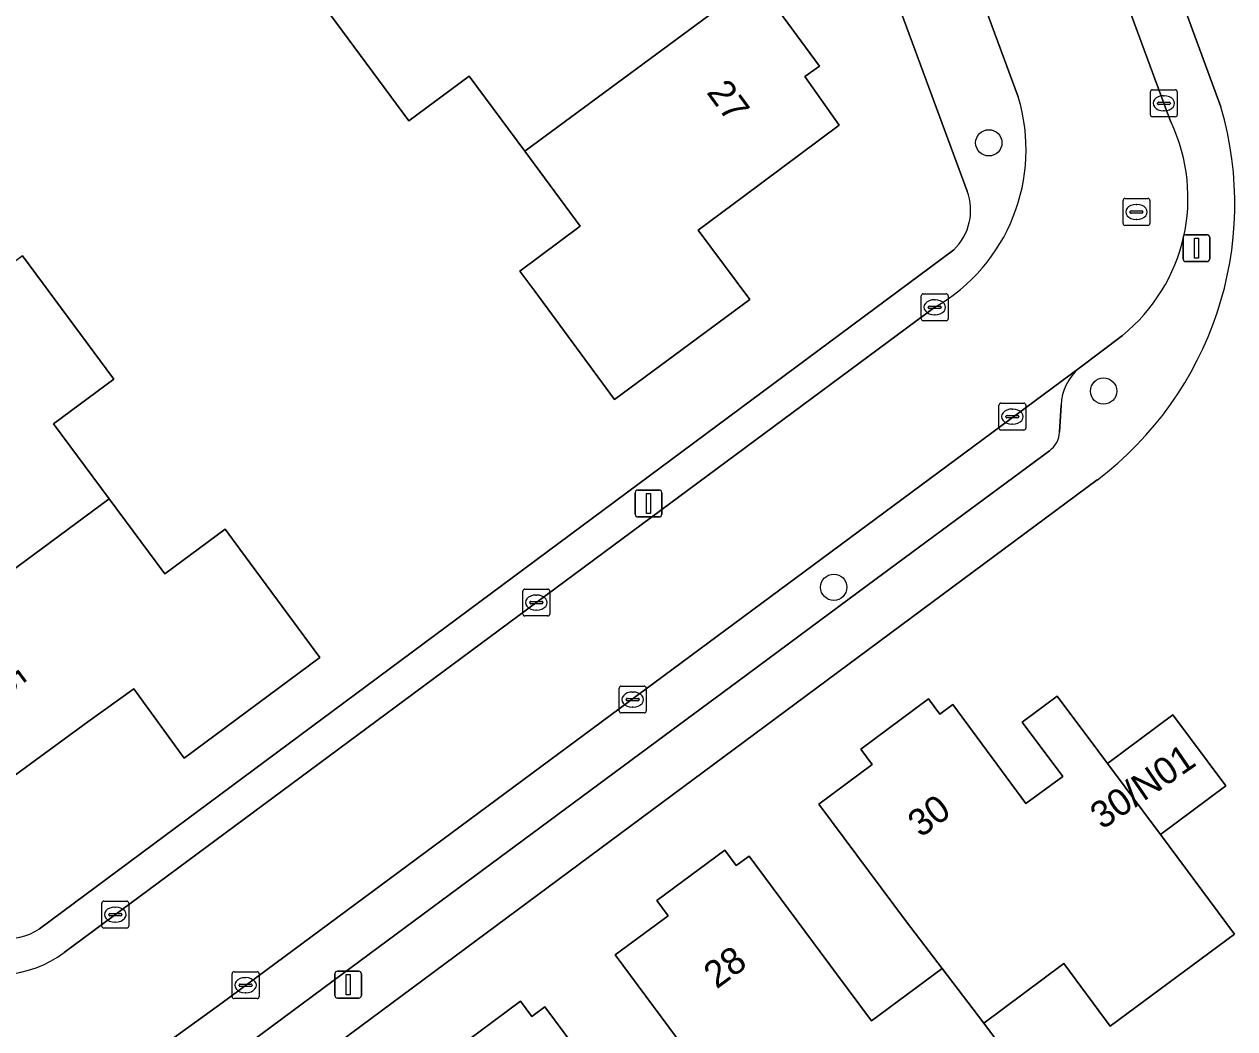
# Model space of a CAD drawing. Extents: x 163426 to 164192, y 380329 to 381641.
# Drawn here: x 163877.32 to 163922.34, y 381126.58 to 381163.93 of the extents above; entities that cross this region are included whole.
import ezdxf

# ---------------------------------------------------------------- set-up
doc = ezdxf.new("R2010")
doc.units = 0
for name, color, linetype in [('IMGEO_Boom', 7, 'Continuous'), ('IMGEO_Erf', 7, 'Continuous'), ('IMGEO_Kolk', 7, 'Continuous'), ('IMGEO_Lichtmast', 7, 'Continuous'), ('IMGEO_Pand', 7, 'Continuous'), ('IMGEO_Pand_nummerreeks', 7, 'Continuous'), ('IMGEO_Parkeervlak_open', 7, 'Continuous'), ('IMGEO_Rijbaan_lokaal_open', 7, 'Continuous'), ('IMGEO_Rioolput', 7, 'Continuous'), ('IMGEO_Voetpad_open', 7, 'Continuous')]:
    doc.layers.add(name, color=color, linetype=linetype)

msp = doc.modelspace()

# ---------------------------------------------------------------- linework, layer by layer
at = {"layer": 'IMGEO_Boom'}
for centre in [(163913.195, 381159.523), (163917.466, 381150.293), (163907.429, 381142.998)]:
    msp.add_circle(centre, 0.489, dxfattribs=at)
at = {"layer": 'IMGEO_Erf'}
for points in [[(163912.458, 381186.339), (163921.831, 381160.861)], [(163912.387, 381157.729), (163904.013, 381180.42)], [(163905.197, 381164.676), (163906.897, 381162.371), (163906.356, 381161.988), (163907.631, 381160.185), (163904.073, 381157.531), (163902.39, 381156.275), (163904.312, 381153.699), (163899.276, 381149.981), (163896.305, 381154.003), (163895.748, 381154.757), (163898, 381156.42), (163895.936, 381159.214), (163893.872, 381162.007), (163891.621, 381160.344), (163888.24, 381164.922)], [(163877.893, 381130.301), (163911.894, 381155.545)], [(163877.25, 381155.325), (163880.651, 381150.737), (163878.411, 381149.076), (163880.48, 381146.285), (163882.549, 381143.494), (163884.789, 381145.156), (163885.342, 381144.41), (163888.32, 381140.393), (163883.272, 381136.64), (163881.394, 381139.227), (163879.691, 381137.99), (163876.101, 381135.383)], [(163917.22, 381146.987), (163884.455, 381122.693), (163883.08, 381121.66), (163882.189, 381120.998)], [(163903.828, 381123.229), (163899.295, 381129.331), (163901.27, 381130.787), (163900.854, 381131.347), (163903.374, 381133.22), (163903.797, 381132.65), (163904.279, 381133.006), (163907.537, 381128.624), (163908.835, 381126.878), (163911.457, 381128.826), (163910.136, 381130.556), (163906.878, 381134.938), (163908.856, 381136.409), (163908.433, 381136.98), (163910.953, 381138.853), (163911.376, 381138.283), (163911.857, 381138.641), (163914.574, 381134.957), (163915.944, 381135.968), (163914.442, 381137.988), (163915.742, 381138.955), (163917.249, 381136.93), (163917.607, 381136.448), (163920.04, 381138.258), (163922.01, 381135.611), (163919.576, 381133.801), (163922.33, 381130.099), (163917.712, 381126.679), (163915.991, 381129.004), (163913.008, 381126.795), (163914.73, 381124.47)], [(163893.26, 381125.735), (163895.78, 381127.608), (163896.203, 381127.038), (163896.685, 381127.394), (163899.951, 381122.993)]]:
    msp.add_lwpolyline(points, dxfattribs=at)
for centre, radius, start, end in [((163909.481, 381157.262), 12.864, 306.9864, 16.2453), ((163910.502, 381157.007), 2.018, 313.594, 20.9653), ((163876.722, 381132.011), 2.072, 216.5753, 304.4017)]:
    msp.add_arc(centre, radius, start, end, dxfattribs=at)
at = {"layer": 'IMGEO_Kolk'}
for p, q in [((163919.205, 381160.568), (163919.205, 381161.42)), ((163919.28, 381161.494), (163920.132, 381161.494)), ((163919.693, 381161.274), (163919.718, 381161.274)), ((163920.206, 381161.42), (163920.206, 381160.568)), ((163919.464, 381160.988), (163919.464, 381161)), ((163919.902, 381160.951), (163919.504, 381160.951)), ((163919.507, 381161.037), (163919.905, 381161.037)), ((163919.948, 381161), (163919.948, 381160.988)), ((163920.132, 381160.494), (163919.28, 381160.494)), ((163919.716, 381160.714), (163919.691, 381160.714)), ((163910.684, 381152.983), (163910.684, 381153.835)), ((163910.759, 381153.909), (163911.611, 381153.909)), ((163911.172, 381153.689), (163911.197, 381153.689)), ((163911.685, 381153.835), (163911.685, 381152.983)), ((163910.943, 381153.403), (163910.943, 381153.415)), ((163911.381, 381153.366), (163910.983, 381153.366)), ((163910.986, 381153.452), (163911.384, 381153.452)), ((163911.195, 381153.129), (163911.17, 381153.129)), ((163911.427, 381153.415), (163911.427, 381153.403)), ((163911.611, 381152.909), (163910.759, 381152.909)), ((163913.572, 381148.918), (163913.572, 381149.77)), ((163913.647, 381149.844), (163914.499, 381149.844)), ((163914.06, 381149.624), (163914.085, 381149.624)), ((163914.573, 381149.77), (163914.573, 381148.918)), ((163913.831, 381149.338), (163913.831, 381149.35)), ((163914.269, 381149.301), (163913.871, 381149.301)), ((163913.874, 381149.387), (163914.272, 381149.387)), ((163914.083, 381149.064), (163914.058, 381149.064)), ((163914.315, 381149.35), (163914.315, 381149.338)), ((163914.499, 381148.844), (163913.647, 381148.844)), ((163895.865, 381142.004), (163895.865, 381142.856)), ((163895.94, 381142.93), (163896.792, 381142.93)), ((163896.866, 381142.856), (163896.866, 381142.004)), ((163896.124, 381142.424), (163896.124, 381142.436)), ((163896.562, 381142.387), (163896.164, 381142.387)), ((163896.167, 381142.473), (163896.565, 381142.473)), ((163896.353, 381142.71), (163896.378, 381142.71)), ((163896.608, 381142.436), (163896.608, 381142.424)), ((163896.792, 381141.93), (163895.94, 381141.93)), ((163896.376, 381142.15), (163896.351, 381142.15)), ((163899.451, 381138.398), (163899.451, 381139.25)), ((163899.526, 381139.324), (163900.378, 381139.324)), ((163900.452, 381139.25), (163900.452, 381138.398)), ((163899.71, 381138.818), (163899.71, 381138.83)), ((163900.148, 381138.781), (163899.75, 381138.781)), ((163899.753, 381138.867), (163900.151, 381138.867)), ((163899.939, 381139.104), (163899.964, 381139.104)), ((163900.194, 381138.83), (163900.194, 381138.818)), ((163900.378, 381138.324), (163899.526, 381138.324)), ((163899.962, 381138.544), (163899.937, 381138.544)), ((163880.205, 381130.401), (163880.205, 381131.253)), ((163880.28, 381131.327), (163881.132, 381131.327)), ((163880.693, 381131.107), (163880.718, 381131.107)), ((163881.206, 381131.253), (163881.206, 381130.401)), ((163880.464, 381130.821), (163880.464, 381130.833)), ((163880.902, 381130.784), (163880.504, 381130.784)), ((163880.507, 381130.87), (163880.905, 381130.87)), ((163880.948, 381130.833), (163880.948, 381130.821)), ((163881.132, 381130.327), (163880.28, 381130.327)), ((163880.716, 381130.547), (163880.691, 381130.547)), ((163885.052, 381127.777), (163885.052, 381128.629)), ((163885.127, 381128.703), (163885.979, 381128.703)), ((163885.54, 381128.483), (163885.565, 381128.483)), ((163886.053, 381128.629), (163886.053, 381127.777)), ((163885.311, 381128.197), (163885.311, 381128.209)), ((163885.749, 381128.16), (163885.351, 381128.16)), ((163885.354, 381128.246), (163885.752, 381128.246)), ((163885.563, 381127.923), (163885.538, 381127.923)), ((163885.795, 381128.209), (163885.795, 381128.197)), ((163885.979, 381127.703), (163885.127, 381127.703))]:
    msp.add_line(p, q, dxfattribs=at)
for points in [[(163919.205, 381160.568), (163919.205, 381161.42)], [(163919.28, 381161.494), (163920.132, 381161.494)], [(163920.206, 381161.42), (163920.206, 381160.568)], [(163920.132, 381160.494), (163919.28, 381160.494)], [(163910.684, 381152.983), (163910.684, 381153.835)], [(163910.759, 381153.909), (163911.611, 381153.909)], [(163911.685, 381153.835), (163911.685, 381152.983)], [(163911.611, 381152.909), (163910.759, 381152.909)], [(163913.572, 381148.918), (163913.572, 381149.77)], [(163913.647, 381149.844), (163914.499, 381149.844)], [(163914.573, 381149.77), (163914.573, 381148.918)], [(163914.499, 381148.844), (163913.647, 381148.844)], [(163895.865, 381142.004), (163895.865, 381142.856)], [(163895.94, 381142.93), (163896.792, 381142.93)], [(163896.866, 381142.856), (163896.866, 381142.004)], [(163896.792, 381141.93), (163895.94, 381141.93)], [(163899.451, 381138.398), (163899.451, 381139.25)], [(163899.526, 381139.324), (163900.378, 381139.324)], [(163900.452, 381139.25), (163900.452, 381138.398)], [(163900.378, 381138.324), (163899.526, 381138.324)], [(163880.205, 381130.401), (163880.205, 381131.253)], [(163880.28, 381131.327), (163881.132, 381131.327)], [(163881.206, 381131.253), (163881.206, 381130.401)], [(163881.132, 381130.327), (163880.28, 381130.327)], [(163885.052, 381127.777), (163885.052, 381128.629)], [(163885.127, 381128.703), (163885.979, 381128.703)], [(163886.053, 381128.629), (163886.053, 381127.777)], [(163885.979, 381127.703), (163885.127, 381127.703)]]:
    msp.add_lwpolyline(points, dxfattribs=at)
for centre, radius, start, end in [((163919.282, 381161.418), 0.0765, 91.552, 178.448), ((163919.282, 381161.418), 0.0765, 91.552, 178.448), ((163920.13, 381161.418), 0.0765, 1.552, 88.448), ((163920.13, 381161.418), 0.0765, 1.552, 88.448), ((163919.504, 381160.997), 0.0403, 85.8775, 175.7526), ((163919.501, 381160.987), 0.0366, 178.938, 274.7102), ((163919.905, 381160.994), 0.043, 264.8664, 352.4533), ((163919.909, 381160.999), 0.0386, 1.7309, 96.639), ((163919.282, 381160.57), 0.0765, 181.552, 268.448), ((163919.282, 381160.57), 0.0765, 181.552, 268.448), ((163920.13, 381160.57), 0.0765, 271.552, 358.448), ((163920.13, 381160.57), 0.0765, 271.552, 358.448), ((163910.761, 381153.833), 0.0765, 91.552, 178.448), ((163910.761, 381153.833), 0.0765, 91.552, 178.448), ((163911.609, 381153.833), 0.0765, 1.552, 88.448), ((163911.609, 381153.833), 0.0765, 1.552, 88.448), ((163910.983, 381153.412), 0.0403, 85.8775, 175.7526), ((163910.98, 381153.402), 0.0366, 178.938, 274.7102), ((163911.384, 381153.409), 0.043, 264.8664, 352.4533), ((163911.388, 381153.414), 0.0386, 1.7309, 96.639), ((163910.761, 381152.985), 0.0765, 181.552, 268.448), ((163910.761, 381152.985), 0.0765, 181.552, 268.448), ((163911.609, 381152.985), 0.0765, 271.552, 358.448), ((163911.609, 381152.985), 0.0765, 271.552, 358.448), ((163913.649, 381149.768), 0.0765, 91.552, 178.448), ((163913.649, 381149.768), 0.0765, 91.552, 178.448), ((163914.497, 381149.768), 0.0765, 1.552, 88.448), ((163914.497, 381149.768), 0.0765, 1.552, 88.448), ((163913.871, 381149.347), 0.0403, 85.8775, 175.7526), ((163913.868, 381149.337), 0.0366, 178.938, 274.7102), ((163914.272, 381149.344), 0.043, 264.8664, 352.4533), ((163914.276, 381149.349), 0.0386, 1.7309, 96.639), ((163913.649, 381148.92), 0.0765, 181.552, 268.448), ((163913.649, 381148.92), 0.0765, 181.552, 268.448), ((163914.497, 381148.92), 0.0765, 271.552, 358.448), ((163914.497, 381148.92), 0.0765, 271.552, 358.448), ((163895.942, 381142.854), 0.0765, 91.552, 178.448), ((163895.942, 381142.854), 0.0765, 91.552, 178.448), ((163896.79, 381142.854), 0.0765, 1.552, 88.448), ((163896.79, 381142.854), 0.0765, 1.552, 88.448), ((163896.164, 381142.433), 0.0403, 85.8775, 175.7526), ((163896.161, 381142.423), 0.0366, 178.938, 274.7102), ((163896.565, 381142.43), 0.043, 264.8664, 352.4533), ((163896.569, 381142.435), 0.0386, 1.7309, 96.639), ((163895.942, 381142.006), 0.0765, 181.552, 268.448), ((163895.942, 381142.006), 0.0765, 181.552, 268.448), ((163896.79, 381142.006), 0.0765, 271.552, 358.448), ((163896.79, 381142.006), 0.0765, 271.552, 358.448), ((163899.528, 381139.248), 0.0765, 91.552, 178.448), ((163899.528, 381139.248), 0.0765, 91.552, 178.448), ((163900.376, 381139.248), 0.0765, 1.552, 88.448), ((163900.376, 381139.248), 0.0765, 1.552, 88.448), ((163899.75, 381138.827), 0.0403, 85.8775, 175.7526), ((163899.747, 381138.817), 0.0366, 178.938, 274.7102), ((163900.151, 381138.824), 0.043, 264.8664, 352.4533), ((163900.155, 381138.829), 0.0386, 1.7309, 96.639), ((163899.528, 381138.4), 0.0765, 181.552, 268.448), ((163899.528, 381138.4), 0.0765, 181.552, 268.448), ((163900.376, 381138.4), 0.0765, 271.552, 358.448), ((163900.376, 381138.4), 0.0765, 271.552, 358.448), ((163880.282, 381131.251), 0.0765, 91.552, 178.448), ((163880.282, 381131.251), 0.0765, 91.552, 178.448), ((163881.13, 381131.251), 0.0765, 1.552, 88.448), ((163881.13, 381131.251), 0.0765, 1.552, 88.448), ((163880.504, 381130.83), 0.0403, 85.8775, 175.7526), ((163880.501, 381130.82), 0.0366, 178.938, 274.7102), ((163880.905, 381130.827), 0.043, 264.8664, 352.4533), ((163880.909, 381130.832), 0.0386, 1.7309, 96.639), ((163880.282, 381130.403), 0.0765, 181.552, 268.448), ((163880.282, 381130.403), 0.0765, 181.552, 268.448), ((163881.13, 381130.403), 0.0765, 271.552, 358.448), ((163881.13, 381130.403), 0.0765, 271.552, 358.448), ((163885.129, 381128.627), 0.0765, 91.552, 178.448), ((163885.129, 381128.627), 0.0765, 91.552, 178.448), ((163885.977, 381128.627), 0.0765, 1.552, 88.448), ((163885.977, 381128.627), 0.0765, 1.552, 88.448), ((163885.351, 381128.206), 0.0403, 85.8775, 175.7526), ((163885.348, 381128.196), 0.0366, 178.938, 274.7102), ((163885.752, 381128.203), 0.043, 264.8664, 352.4533), ((163885.756, 381128.208), 0.0386, 1.7309, 96.639), ((163885.129, 381127.779), 0.0765, 181.552, 268.448), ((163885.129, 381127.779), 0.0765, 181.552, 268.448), ((163885.977, 381127.779), 0.0765, 271.552, 358.448), ((163885.977, 381127.779), 0.0765, 271.552, 358.448)]:
    msp.add_arc(centre, radius, start, end, dxfattribs=at)
for centre, major_axis, ratio, start_param, end_param in [((163919.692, 381160.994), (-0.387, 0.002), 0.722429, 4.712389, 7.853982), ((163919.717, 381160.994), (-0.39, 0.002), 0.717154, 1.570796, 4.712389), ((163911.171, 381153.409), (-0.387, 0.002), 0.722429, 4.712389, 7.853982), ((163911.196, 381153.409), (-0.39, 0.002), 0.717154, 1.570796, 4.712389), ((163914.059, 381149.344), (-0.387, 0.002), 0.722429, 4.712389, 7.853982), ((163914.084, 381149.344), (-0.39, 0.002), 0.717154, 1.570796, 4.712389), ((163896.352, 381142.43), (-0.387, 0.002), 0.722429, 4.712389, 7.853982), ((163896.377, 381142.43), (-0.39, 0.002), 0.717154, 1.570796, 4.712389), ((163899.938, 381138.824), (-0.387, 0.002), 0.722429, 4.712389, 7.853982), ((163899.963, 381138.824), (-0.39, 0.002), 0.717154, 1.570796, 4.712389), ((163880.692, 381130.827), (-0.387, 0.002), 0.722429, 4.712389, 7.853982), ((163880.717, 381130.827), (-0.39, 0.002), 0.717154, 1.570796, 4.712389), ((163885.539, 381128.203), (-0.387, 0.002), 0.722429, 4.712389, 7.853982), ((163885.564, 381128.203), (-0.39, 0.002), 0.717154, 1.570796, 4.712389)]:
    msp.add_ellipse(centre, major_axis=major_axis, ratio=ratio, start_param=start_param, end_param=end_param, dxfattribs=at)
at = {"layer": 'IMGEO_Lichtmast'}
for p, q in [((163920.422, 381155.207), (163920.422, 381156.007)), ((163920.422, 381156.007), (163920.422, 381155.207)), ((163920.522, 381156.107), (163921.312, 381156.107)), ((163921.312, 381156.107), (163920.522, 381156.107)), ((163921.412, 381156.007), (163921.412, 381155.207)), ((163921.412, 381155.207), (163921.412, 381156.007)), ((163921.312, 381155.107), (163920.522, 381155.107)), ((163920.522, 381155.107), (163921.312, 381155.107)), ((163900.044, 381145.714), (163900.044, 381146.514)), ((163900.044, 381146.514), (163900.044, 381145.714)), ((163900.144, 381146.614), (163900.934, 381146.614)), ((163900.934, 381146.614), (163900.144, 381146.614)), ((163901.034, 381146.514), (163901.034, 381145.714)), ((163901.034, 381145.714), (163901.034, 381146.514)), ((163900.934, 381145.614), (163900.144, 381145.614)), ((163900.144, 381145.614), (163900.934, 381145.614)), ((163888.871, 381127.825), (163888.871, 381128.625)), ((163888.871, 381128.625), (163888.871, 381127.825)), ((163888.971, 381128.725), (163889.761, 381128.725)), ((163889.761, 381128.725), (163888.971, 381128.725)), ((163889.861, 381128.625), (163889.861, 381127.825)), ((163889.861, 381127.825), (163889.861, 381128.625)), ((163889.761, 381127.725), (163888.971, 381127.725)), ((163888.971, 381127.725), (163889.761, 381127.725))]:
    msp.add_line(p, q, dxfattribs=at)
for points in [[(163920.842, 381155.982), (163920.992, 381155.982), (163920.992, 381155.232), (163920.842, 381155.232), (163920.842, 381155.982)], [(163900.464, 381146.489), (163900.614, 381146.489), (163900.614, 381145.739), (163900.464, 381145.739), (163900.464, 381146.489)], [(163889.291, 381128.6), (163889.441, 381128.6), (163889.441, 381127.85), (163889.291, 381127.85), (163889.291, 381128.6)]]:
    msp.add_lwpolyline(points, dxfattribs=at)
for centre, start, end in [((163920.522, 381156.007), 90, 180), ((163920.522, 381156.007), 90, 180), ((163921.312, 381156.007), 0, 90), ((163921.312, 381156.007), 360, 90), ((163920.522, 381155.207), 180, 270), ((163920.522, 381155.207), 180, 270), ((163921.312, 381155.207), 270, 0), ((163921.312, 381155.207), 270, 0), ((163900.144, 381146.514), 90, 180), ((163900.144, 381146.514), 90, 180), ((163900.934, 381146.514), 0, 90), ((163900.934, 381146.514), 360, 90), ((163900.144, 381145.714), 180, 270), ((163900.144, 381145.714), 180, 270), ((163900.934, 381145.714), 270, 0), ((163900.934, 381145.714), 270, 0), ((163888.971, 381128.625), 90, 180), ((163888.971, 381128.625), 90, 180), ((163889.761, 381128.625), 0, 90), ((163889.761, 381128.625), 360, 90), ((163888.971, 381127.825), 180, 270), ((163888.971, 381127.825), 180, 270), ((163889.761, 381127.825), 270, 0), ((163889.761, 381127.825), 270, 0)]:
    msp.add_arc(centre, 0.1, start, end, dxfattribs=at)
at = {"layer": 'IMGEO_Pand'}
for points in [[(163893.368, 381168.698), (163888.24, 381164.922), (163891.621, 381160.344), (163893.872, 381162.007), (163895.936, 381159.214), (163904.008, 381165.174), (163903.352, 381166.064), (163903.884, 381166.456), (163902.178, 381168.769), (163901.651, 381168.373), (163900.332, 381170.131), (163895.131, 381166.302)], [(163907.631, 381160.185), (163906.356, 381161.988), (163906.897, 381162.371), (163905.197, 381164.676), (163904.665, 381164.283), (163904.008, 381165.174), (163895.936, 381159.214), (163898, 381156.42), (163895.748, 381154.757), (163896.305, 381154.003), (163899.276, 381149.981), (163904.312, 381153.699), (163902.39, 381156.275), (163904.073, 381157.531)], [(163878.411, 381149.076), (163880.651, 381150.737), (163877.25, 381155.325), (163872.254, 381151.606), (163874.035, 381149.212), (163872.325, 381147.94), (163868.749, 381145.28), (163870.056, 381143.503), (163869.523, 381143.111), (163871.224, 381140.814), (163871.754, 381141.206), (163872.408, 381140.322), (163880.48, 381146.285)], [(163885.342, 381144.41), (163884.789, 381145.156), (163882.549, 381143.494), (163880.48, 381146.285), (163872.408, 381140.322), (163873.062, 381139.439), (163872.532, 381139.046), (163874.239, 381136.741), (163874.767, 381137.141), (163876.101, 381135.383), (163879.691, 381137.99), (163881.394, 381139.227), (163883.272, 381136.64), (163888.32, 381140.393)], [(163919.576, 381133.801), (163917.607, 381136.448), (163917.249, 381136.93), (163915.742, 381138.955), (163914.442, 381137.988), (163915.944, 381135.968), (163914.574, 381134.957), (163911.857, 381138.641), (163911.376, 381138.283), (163910.953, 381138.853), (163908.433, 381136.98), (163908.856, 381136.409), (163906.878, 381134.938), (163910.136, 381130.556), (163911.457, 381128.826), (163913.008, 381126.795), (163915.991, 381129.004), (163917.712, 381126.679), (163922.33, 381130.099)], [(163917.607, 381136.448), (163919.576, 381133.801), (163922.01, 381135.611), (163920.04, 381138.258)], [(163907.537, 381128.624), (163904.279, 381133.006), (163903.797, 381132.65), (163903.374, 381133.22), (163900.854, 381131.347), (163901.27, 381130.787), (163899.295, 381129.331), (163903.828, 381123.229), (163907.102, 381118.82), (163914.73, 381124.47), (163913.008, 381126.795), (163911.457, 381128.826), (163908.835, 381126.878)], [(163899.951, 381122.993), (163896.685, 381127.394), (163896.203, 381127.038), (163895.78, 381127.608), (163893.26, 381125.735), (163893.678, 381125.171), (163891.703, 381123.71), (163894.963, 381119.295), (163896.246, 381117.63), (163897.841, 381115.561), (163900.823, 381117.77), (163902.545, 381115.445), (163907.102, 381118.82), (163903.828, 381123.229), (163901.215, 381121.29)]]:
    msp.add_lwpolyline(points, close=True, dxfattribs=at)
at = {"layer": 'IMGEO_Parkeervlak_open'}
for points in [[(163916.554, 381151.141), (163884.68, 381127.548), (163880.923, 381124.832)], [(163915.823, 381148.771), (163915.886, 381149.771)], [(163884.183, 381124.937), (163885.739, 381126.089), (163888.806, 381128.36), (163893.166, 381131.587), (163896.214, 381133.842), (163900.842, 381137.267), (163903.871, 381139.507), (163908.391, 381142.852), (163911.422, 381145.095), (163915.45, 381148.075)]]:
    msp.add_lwpolyline(points, dxfattribs=at)
for centre, radius, start, end in [((163917.732, 381149.719), 1.847, 129.6332, 178.3799), ((163914.954, 381148.789), 0.869, 304.7945, 358.83)]:
    msp.add_arc(centre, radius, start, end, dxfattribs=at)
at = {"layer": 'IMGEO_Rijbaan_lokaal_open'}
for points in [[(163919.972, 381160.287), (163910.883, 381184.915), (163910.621, 381185.625), (163905.959, 381183.862), (163906.205, 381183.194), (163912.987, 381164.75), (163914.289, 381161.234)], [(163911.186, 381153.408), (163878.809, 381129.42)], [(163880.923, 381124.832), (163884.68, 381127.548), (163916.554, 381151.141), (163918.164, 381152.365)]]:
    msp.add_lwpolyline(points, dxfattribs=at)
for centre, radius, start, end in [((163907.832, 381159.266), 6.75, 299.793, 16.9505), ((163914.032, 381157.475), 6.572, 308.9593, 25.3284), ((163876.27, 381132.847), 4.266, 242.8159, 306.5339)]:
    msp.add_arc(centre, radius, start, end, dxfattribs=at)
at = {"layer": 'IMGEO_Rioolput'}
for p, q in [((163918.187, 381156.527), (163918.187, 381157.379)), ((163918.262, 381157.453), (163919.114, 381157.453)), ((163918.675, 381157.233), (163918.7, 381157.233)), ((163919.188, 381157.379), (163919.188, 381156.527)), ((163918.446, 381156.947), (163918.446, 381156.959)), ((163918.884, 381156.91), (163918.486, 381156.91)), ((163918.489, 381156.996), (163918.887, 381156.996)), ((163918.93, 381156.959), (163918.93, 381156.947)), ((163919.114, 381156.453), (163918.262, 381156.453)), ((163918.698, 381156.673), (163918.673, 381156.673))]:
    msp.add_line(p, q, dxfattribs=at)
for points in [[(163918.187, 381156.527), (163918.187, 381157.379)], [(163918.262, 381157.453), (163919.114, 381157.453)], [(163919.188, 381157.379), (163919.188, 381156.527)], [(163919.114, 381156.453), (163918.262, 381156.453)]]:
    msp.add_lwpolyline(points, dxfattribs=at)
for centre, radius, start, end in [((163918.264, 381157.377), 0.0765, 91.552, 178.448), ((163918.264, 381157.377), 0.0765, 91.552, 178.448), ((163919.112, 381157.377), 0.0765, 1.552, 88.448), ((163919.112, 381157.377), 0.0765, 1.552, 88.448), ((163918.486, 381156.956), 0.0403, 85.8775, 175.7526), ((163918.483, 381156.946), 0.0366, 178.938, 274.7102), ((163918.887, 381156.953), 0.043, 264.8664, 352.4533), ((163918.891, 381156.958), 0.0386, 1.7309, 96.639), ((163918.264, 381156.529), 0.0765, 181.552, 268.448), ((163918.264, 381156.529), 0.0765, 181.552, 268.448), ((163919.112, 381156.529), 0.0765, 271.552, 358.448), ((163919.112, 381156.529), 0.0765, 271.552, 358.448)]:
    msp.add_arc(centre, radius, start, end, dxfattribs=at)
for centre, major_axis, ratio, start_param, end_param in [((163918.674, 381156.953), (-0.387, 0.002), 0.722429, 4.712389, 7.853982), ((163918.699, 381156.953), (-0.39, 0.002), 0.717154, 1.570796, 4.712389)]:
    msp.add_ellipse(centre, major_axis=major_axis, ratio=ratio, start_param=start_param, end_param=end_param, dxfattribs=at)
at = {"layer": 'IMGEO_Voetpad_open'}
for points in [[(163921.831, 381160.861), (163912.458, 381186.339), (163910.621, 381185.625), (163910.883, 381184.915), (163919.972, 381160.287)], [(163902.765, 381183.681), (163904.013, 381180.42), (163912.387, 381157.729)], [(163914.289, 381161.234), (163912.987, 381164.75)], [(163911.894, 381155.545), (163877.893, 381130.301)], [(163878.809, 381129.42), (163911.186, 381153.408)], [(163918.164, 381152.365), (163916.554, 381151.141)], [(163915.886, 381149.771), (163915.823, 381148.771)], [(163915.45, 381148.075), (163911.422, 381145.095), (163908.391, 381142.852), (163903.871, 381139.507), (163900.842, 381137.267), (163896.214, 381133.842), (163893.166, 381131.587), (163888.806, 381128.36), (163885.739, 381126.089), (163884.183, 381124.937)], [(163854.6, 381141.786), (163874.338, 381115.123), (163875.27, 381115.855), (163879.294, 381118.846), (163882.189, 381120.998), (163883.08, 381121.66), (163884.455, 381122.693), (163917.22, 381146.987)]]:
    msp.add_lwpolyline(points, dxfattribs=at)
for centre, radius, start, end in [((163907.832, 381159.266), 6.75, 299.793, 16.9505), ((163909.481, 381157.262), 12.864, 306.9864, 16.2453), ((163914.032, 381157.475), 6.572, 308.9593, 25.3284), ((163910.502, 381157.007), 2.018, 313.594, 20.9653), ((163917.732, 381149.719), 1.847, 129.6332, 178.3799), ((163914.954, 381148.789), 0.869, 304.7945, 358.83), ((163876.722, 381132.011), 2.072, 216.5753, 304.4017), ((163876.27, 381132.847), 4.266, 242.8159, 306.5339)]:
    msp.add_arc(centre, radius, start, end, dxfattribs=at)

# ---------------------------------------------------------------- texts
at = {"layer": 'IMGEO_Pand_nummerreeks'}
for s, rotation, p in [('27', 306.2737, (163902.673, 381161.397)), ('25', 306.6061, (163875.794, 381140.024)), ('30/N01', 34.4184, (163917.414, 381133.967)), ('30', 36.6407, (163910.664, 381133.667)), ('28', 36.4057, (163903.072, 381128.04))]:
    msp.add_text(s, height=1, rotation=rotation, dxfattribs=at).set_placement(p)

doc.saveas('drawing.dxf')
